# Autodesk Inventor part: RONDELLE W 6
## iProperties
Created: 2004-11
Part Number: RONDELLE W 6
Document SubType Name: Modeling
Designer: Bruno
Manufacturer: Standard
Standards Organization: Custom
Author: Bruno
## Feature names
1. Base1
